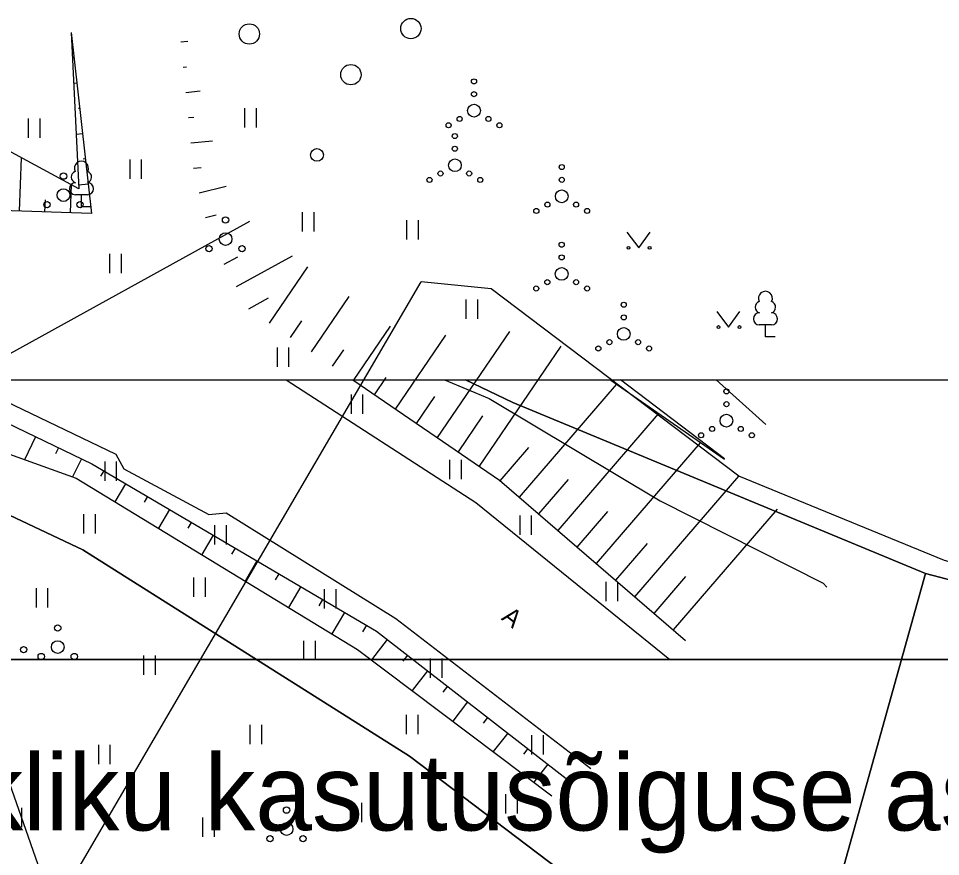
# Model space of a CAD drawing. Extents: x 554947 to 555436, y 6564938 to 6565792.
# Drawn here: x 555027.7 to 555064.02, y 6565636.15 to 6565669.14 of the extents above; entities that cross this region are included whole.
import ezdxf

# ---------------------------------------------------------------- set-up
doc = ezdxf.new("R2010")
doc.units = 0
for name, color, linetype in [('AED', 7, 'Continuous'), ('HALJASTUS', 7, 'Continuous'), ('KPKAABEL', 7, 'Continuous'), ('MPKAABEL', 7, 'Continuous'), ('PIIR', 7, 'Continuous'), ('POST', 7, 'Continuous'), ('PR_SIDE', 7, 'Continuous'), ('PUU', 7, 'Continuous'), ('RELJEEF', 7, 'Continuous'), ('TEE', 7, 'Continuous'), ('VORMISTUS_2', 7, 'Continuous')]:
    doc.layers.add(name, color=color, linetype=linetype)

msp = doc.modelspace()

# ---------------------------------------------------------------- linework, layer by layer
at = {"layer": 'AED'}
msp.add_lwpolyline([(555057.142, 6565653.162), (555055.18, 6565654.913)], dxfattribs=at)
at = {"layer": 'HALJASTUS'}
for p, q in [((555036.611, 6565665.617), (555036.611, 6565664.856)), ((555037.066, 6565665.617), (555037.066, 6565664.856)), ((555028.088, 6565665.207), (555028.088, 6565664.446)), ((555028.543, 6565665.207), (555028.543, 6565664.446)), ((555032.085, 6565663.593), (555032.085, 6565662.832)), ((555032.54, 6565663.593), (555032.54, 6565662.832)), ((555038.874, 6565661.521), (555038.874, 6565660.76)), ((555039.329, 6565661.521), (555039.329, 6565660.76)), ((555042.991, 6565661.208), (555042.991, 6565660.447)), ((555043.446, 6565661.208), (555043.446, 6565660.447)), ((555051.669, 6565660.724), (555052.133, 6565660.117)), ((555052.133, 6565660.117), (555052.578, 6565660.724)), ((555031.29, 6565659.883), (555031.29, 6565659.122)), ((555031.745, 6565659.883), (555031.745, 6565659.122)), ((555045.327, 6565658.076), (555045.327, 6565657.315)), ((555045.782, 6565658.076), (555045.782, 6565657.315)), ((555055.209, 6565657.604), (555055.672, 6565656.997)), ((555055.672, 6565656.997), (555056.118, 6565657.604)), ((555037.887, 6565656.197), (555037.887, 6565655.436)), ((555038.342, 6565656.197), (555038.342, 6565655.436)), ((555040.8, 6565654.342), (555040.8, 6565653.581)), ((555041.255, 6565654.342), (555041.255, 6565653.581)), ((555031.098, 6565651.706), (555031.098, 6565650.945)), ((555031.553, 6565651.706), (555031.553, 6565650.945)), ((555044.676, 6565651.764), (555044.676, 6565651.003)), ((555045.132, 6565651.764), (555045.132, 6565651.003)), ((555030.263, 6565649.635), (555030.263, 6565648.874)), ((555030.718, 6565649.635), (555030.718, 6565648.874)), ((555047.445, 6565649.572), (555047.445, 6565648.811)), ((555047.9, 6565649.572), (555047.9, 6565648.811)), ((555035.423, 6565649.197), (555035.423, 6565648.436)), ((555035.878, 6565649.197), (555035.878, 6565648.436)), ((555034.597, 6565647.143), (555034.597, 6565646.381)), ((555035.052, 6565647.143), (555035.052, 6565646.381)), ((555028.397, 6565646.712), (555028.397, 6565645.951)), ((555028.852, 6565646.712), (555028.852, 6565645.951)), ((555039.741, 6565646.676), (555039.741, 6565645.915)), ((555040.196, 6565646.676), (555040.196, 6565645.915)), ((555050.84, 6565646.97), (555050.84, 6565646.209)), ((555051.295, 6565646.97), (555051.295, 6565646.209)), ((555038.932, 6565644.65), (555038.932, 6565643.889)), ((555039.387, 6565644.65), (555039.387, 6565643.889)), ((555032.631, 6565644.07), (555032.631, 6565643.309)), ((555033.086, 6565644.07), (555033.086, 6565643.309)), ((555043.92, 6565643.947), (555043.92, 6565643.186)), ((555044.375, 6565643.947), (555044.375, 6565643.186)), ((555042.975, 6565641.729), (555042.975, 6565640.968)), ((555043.43, 6565641.729), (555043.43, 6565640.968)), ((555036.817, 6565641.336), (555036.817, 6565640.575)), ((555037.272, 6565641.336), (555037.272, 6565640.575)), ((555047.907, 6565640.93), (555047.907, 6565640.169)), ((555048.362, 6565640.93), (555048.362, 6565640.169)), ((555030.852, 6565640.558), (555030.852, 6565639.797)), ((555031.307, 6565640.558), (555031.307, 6565639.797)), ((555040.764, 6565638.275), (555040.764, 6565637.514)), ((555041.219, 6565638.275), (555041.219, 6565637.514)), ((555046.886, 6565638.615), (555046.886, 6565637.853)), ((555047.341, 6565638.615), (555047.341, 6565637.853)), ((555027.824, 6565638.07), (555027.824, 6565637.309)), ((555028.279, 6565638.07), (555028.279, 6565637.309)), ((555034.953, 6565637.697), (555034.953, 6565636.936)), ((555035.408, 6565637.697), (555035.408, 6565636.936))]:
    msp.add_line(p, q, dxfattribs=at)
msp.add_lwpolyline([(555055.505, 6565651.803), (555051.413, 6565654.913)], dxfattribs=at)
for centre, radius in [((555043.157, 6565668.742), 0.4), ((555036.795, 6565668.531), 0.4), ((555040.797, 6565666.929), 0.4), ((555045.644, 6565666.663), 0.1), ((555045.644, 6565666.163), 0.1), ((555045.644, 6565665.513), 0.25), ((555045.079, 6565665.188), 0.1), ((555046.209, 6565665.188), 0.1), ((555044.644, 6565664.938), 0.1), ((555046.644, 6565664.938), 0.1), ((555044.89, 6565664.513), 0.1), ((555044.89, 6565664.013), 0.1), ((555044.89, 6565663.363), 0.25), ((555049.099, 6565663.291), 0.1), ((555044.325, 6565663.038), 0.1), ((555045.455, 6565663.038), 0.1), ((555043.89, 6565662.788), 0.1), ((555045.89, 6565662.788), 0.1), ((555049.099, 6565662.791), 0.1), ((555049.099, 6565662.141), 0.25), ((555048.534, 6565661.816), 0.1), ((555049.664, 6565661.816), 0.1), ((555048.099, 6565661.566), 0.1), ((555050.099, 6565661.566), 0.1), ((555049.097, 6565660.237), 0.1), ((555051.732, 6565660.117), 0.055), ((555052.561, 6565660.117), 0.055), ((555049.097, 6565659.737), 0.1), ((555049.097, 6565659.087), 0.25), ((555048.097, 6565658.512), 0.1), ((555048.532, 6565658.762), 0.1), ((555049.662, 6565658.762), 0.1), ((555050.097, 6565658.512), 0.1), ((555051.541, 6565657.876), 0.1), ((555051.541, 6565657.376), 0.1), ((555051.541, 6565656.726), 0.25), ((555055.271, 6565656.997), 0.055), ((555056.1, 6565656.997), 0.055), ((555050.976, 6565656.401), 0.1), ((555052.106, 6565656.401), 0.1), ((555050.541, 6565656.151), 0.1), ((555052.541, 6565656.151), 0.1), ((555055.586, 6565654.461), 0.1), ((555055.586, 6565653.961), 0.1), ((555055.586, 6565653.311), 0.25), ((555054.586, 6565652.736), 0.1), ((555055.021, 6565652.986), 0.1), ((555056.151, 6565652.986), 0.1), ((555056.586, 6565652.736), 0.1)]:
    msp.add_circle(centre, radius, dxfattribs=at)
at = {"layer": 'KPKAABEL'}
msp.add_lwpolyline([(555022.085, 6565654.913), (555021.622, 6565652.627), (555021.526, 6565649.765), (555022.786, 6565647.231), (555026.485, 6565641.465), (555030.606, 6565629.728), (555035.378, 6565618.813), (555040.844, 6565608.057), (555047.089, 6565597.805), (555053.567, 6565587.292), (555056.073, 6565583.696), (555062.108, 6565572.667), (555068.248, 6565560.982), (555073.771, 6565549.852), (555080.106, 6565537.978), (555085.958, 6565527.605), (555092.403, 6565515.607), (555098.402, 6565504.536), (555104.641, 6565492.438), (555110.839, 6565480.82), (555116.697, 6565469.072), (555121.821, 6565458.116), (555126.894, 6565446.731), (555132.737, 6565435.388)], dxfattribs=at)
at = {"layer": 'MPKAABEL'}
msp.add_lwpolyline([(555044.483, 6565654.913), (555046.244, 6565654.185), (555052.975, 6565650.153), (555059.391, 6565646.912), (555059.541, 6565646.762)], dxfattribs=at)
at = {"layer": 'PIIR'}
for points in [[(555016.055, 6565654.913), (555030.24, 6565648.23), (555043.11, 6565640.11), (555053.62, 6565632.14), (555056.61, 6565622.91), (555057.22, 6565600.73), (555060.42, 6565583.26), (555065.78, 6565566.7), (555076.76, 6565542.38), (555113.82, 6565475.68), (554946.63, 6565420.78), (554981.01, 6565316.76), (555160.07, 6565375.54), (555166.64, 6565360.5), (555167.67, 6565357.913)], [(555045.31, 6565654.913), (555047.17, 6565654.02), (555063.43, 6565647.29), (555056.61, 6565622.91), (555053.62, 6565632.14), (555043.11, 6565640.11), (555030.24, 6565648.23), (555016.055, 6565654.913)], [(555140.201, 6565654.913), (555137.2, 6565645.72), (555136.5, 6565633.07), (555130.73, 6565621.32), (555129.77, 6565611.2), (555114.24, 6565634), (555063.43, 6565647.29), (555047.17, 6565654.02), (555045.31, 6565654.913)], [(555144.16, 6565410.6), (555124.27, 6565454.45), (555113.82, 6565475.68), (555076.76, 6565542.38), (555065.78, 6565566.7), (555060.42, 6565583.26), (555057.22, 6565600.73), (555056.61, 6565622.91), (555063.43, 6565647.29), (555114.24, 6565634), (555129.77, 6565611.2), (555130.73, 6565621.32), (555138.66, 6565615.26), (555160.12, 6565598.86), (555193.24, 6565604.68), (555193.7, 6565602.7), (555225.47, 6565605.89), (555234.35, 6565605.6), (555251.24, 6565598.48), (555330.71, 6565538.85), (555343.81, 6565536.56), (555350.68, 6565540.44), (555361.56, 6565549.57), (555393.069, 6565582.099)]]:
    msp.add_lwpolyline(points, dxfattribs=at)
at = {"layer": 'POST'}
msp.add_circle((555039.46, 6565663.773), 0.25, dxfattribs=at)
at = {"layer": 'PR_SIDE'}
for points in [[(555136.7, 6565433.435), (555128.282, 6565452.724), (555120.742, 6565469.061), (555112.406, 6565484.723), (555103.739, 6565501.239), (555091.881, 6565522.261), (555081.894, 6565540.539), (555077.43, 6565548.48), (555070.988, 6565563.058), (555062.867, 6565584.513), (555061.059, 6565592.839), (555060.376, 6565594.02), (555051.547, 6565599.57), (555040.593, 6565606.013), (555035.25, 6565616.948), (555028.135, 6565630.971), (555028.178, 6565632.46), (555043.563, 6565658.774)], [(555093.45, 6565648.677), (555083.692, 6565642.526), (555064.179, 6565647.804), (555056.079, 6565651.133), (555046.326, 6565658.494), (555043.563, 6565658.774)]]:
    msp.add_lwpolyline(points, dxfattribs=at)
at = {"layer": 'PUU'}
for p, q in [((555030.422, 6565662.201), (555029.942, 6565662.201)), ((555030.182, 6565661.726), (555030.182, 6565662.201)), ((555030.562, 6565661.726), (555030.182, 6565661.726)), ((555057.361, 6565657.08), (555056.881, 6565657.08)), ((555057.121, 6565656.605), (555057.121, 6565657.08)), ((555057.501, 6565656.605), (555057.121, 6565656.605))]:
    msp.add_line(p, q, dxfattribs=at)
for centre, radius in [((555029.476, 6565662.937), 0.125), ((555029.476, 6565662.187), 0.25), ((555028.826, 6565661.812), 0.125), ((555030.126, 6565661.812), 0.125), ((555035.859, 6565661.208), 0.125), ((555035.859, 6565660.458), 0.25), ((555035.209, 6565660.083), 0.125), ((555036.509, 6565660.083), 0.125), ((555029.249, 6565645.151), 0.125), ((555029.249, 6565644.401), 0.25), ((555027.906, 6565644.299), 0.125), ((555028.599, 6565644.026), 0.125), ((555029.899, 6565644.026), 0.125), ((555038.26, 6565637.984), 0.125), ((555038.26, 6565637.234), 0.25), ((555037.61, 6565636.859), 0.125), ((555038.91, 6565636.859), 0.125)]:
    msp.add_circle(centre, radius, dxfattribs=at)
for centre, radius, start, end in [((555030.182, 6565663.246), 0.277, 332.5799, 207.4201), ((555030.012, 6565662.899), 0.233, 109.0217, 253.1415), ((555030.352, 6565662.899), 0.233, 286.8508, 70.9859), ((555029.944, 6565662.439), 0.238, 90.0016, 269.3953), ((555030.419, 6565662.439), 0.238, 270.6047, 89.9984), ((555057.121, 6565658.125), 0.277, 332.5799, 207.4201), ((555056.951, 6565657.777), 0.233, 109.0217, 253.1415), ((555057.292, 6565657.777), 0.233, 286.8508, 70.9859), ((555056.884, 6565657.317), 0.238, 90.0016, 269.3953), ((555057.359, 6565657.317), 0.238, 270.6047, 89.9984)]:
    msp.add_arc(centre, radius, start, end, dxfattribs=at)
at = {"layer": 'RELJEEF'}
for p, q in [((555034.094, 6565668.222), (555034.378, 6565668.251)), ((555029.894, 6565667.589), (555029.875, 6565667.587)), ((555034.194, 6565667.227), (555034.322, 6565667.24)), ((555030.005, 6565666.595), (555029.88, 6565666.581)), ((555034.294, 6565666.232), (555034.863, 6565666.29)), ((555030.116, 6565665.601), (555030.06, 6565665.595)), ((555034.395, 6565665.237), (555034.608, 6565665.259)), ((555030.227, 6565664.607), (555029.978, 6565664.579)), ((555034.495, 6565664.242), (555035.348, 6565664.328)), ((555027.747, 6565661.559), (555027.82, 6565663.662)), ((555030.338, 6565663.613), (555030.244, 6565663.603)), ((555034.595, 6565663.247), (555034.893, 6565663.277)), ((555029.745, 6565661.489), (555029.785, 6565662.602)), ((555030.448, 6565662.62), (555030.075, 6565662.578)), ((555034.815, 6565662.274), (555035.879, 6565662.546)), ((555028.746, 6565661.524), (555028.763, 6565662.006)), ((555025.494, 6565654.913), (555036.813, 6565661.164)), ((555035.063, 6565661.305), (555035.486, 6565661.413)), ((555035.804, 6565659.465), (555036.34, 6565659.761)), ((555036.288, 6565658.589), (555038.489, 6565659.805)), ((555037.592, 6565657.146), (555039.103, 6565659.364)), ((555036.771, 6565657.714), (555037.556, 6565658.148)), ((555039.245, 6565656.02), (555040.728, 6565658.196)), ((555038.419, 6565656.583), (555038.868, 6565657.242)), ((555040.898, 6565654.894), (555042.352, 6565657.028)), ((555044.204, 6565652.642), (555047.053, 6565656.823)), ((555042.551, 6565653.768), (555044.529, 6565656.67)), ((555040.072, 6565655.457), (555040.512, 6565656.103)), ((555045.856, 6565651.515), (555049.075, 6565656.24)), ((555041.724, 6565654.331), (555042.187, 6565655.01)), ((555047.438, 6565650.296), (555051.257, 6565654.729)), ((555043.377, 6565653.205), (555044.101, 6565654.267)), ((555048.953, 6565648.99), (555052.911, 6565653.584)), ((555045.03, 6565652.078), (555045.997, 6565653.498)), ((555028.377, 6565652.677), (555027.942, 6565651.775)), ((555050.468, 6565647.685), (555054.564, 6565652.439)), ((555029.278, 6565652.243), (555029.161, 6565652)), ((555046.68, 6565650.949), (555047.805, 6565652.254)), ((555030.179, 6565651.808), (555029.835, 6565651.095)), ((555031.059, 6565651.335), (555030.935, 6565651.125)), ((555048.195, 6565649.643), (555049.362, 6565650.997)), ((555051.983, 6565646.379), (555056.079, 6565651.133)), ((555031.921, 6565650.828), (555031.502, 6565650.115)), ((555032.783, 6565650.322), (555032.655, 6565650.104)), ((555033.646, 6565649.816), (555033.212, 6565649.076)), ((555049.71, 6565648.338), (555050.919, 6565649.74)), ((555053.498, 6565645.074), (555057.594, 6565649.828)), ((555034.508, 6565649.309), (555034.375, 6565649.084)), ((555035.37, 6565648.803), (555034.921, 6565648.037)), ((555051.225, 6565647.032), (555052.475, 6565648.482)), ((555036.233, 6565648.297), (555036.096, 6565648.063)), ((555037.095, 6565647.79), (555036.63, 6565646.998)), ((555037.957, 6565647.284), (555037.816, 6565647.042)), ((555052.741, 6565645.727), (555053.99, 6565647.177)), ((555038.82, 6565646.778), (555038.339, 6565645.959)), ((555039.682, 6565646.271), (555039.536, 6565646.022)), ((555040.544, 6565645.765), (555040.048, 6565644.92)), ((555041.407, 6565645.258), (555041.256, 6565645.001)), ((555042.23, 6565644.695), (555041.608, 6565643.893)), ((555043.02, 6565644.082), (555042.836, 6565643.845)), ((555043.81, 6565643.469), (555043.206, 6565642.69)), ((555044.6, 6565642.855), (555044.422, 6565642.625)), ((555045.39, 6565642.242), (555044.804, 6565641.487)), ((555046.18, 6565641.629), (555046.007, 6565641.406)), ((555046.97, 6565641.016), (555046.402, 6565640.284)), ((555047.76, 6565640.403), (555047.592, 6565640.187)), ((555048.55, 6565639.79), (555048, 6565639.082))]:
    msp.add_line(p, q, dxfattribs=at)
for points in [[(555029.783, 6565668.583), (555030.578, 6565661.46), (555027.05, 6565661.583), (555020.786, 6565664.508)], [(555029.783, 6565668.583), (555030.081, 6565662.441), (555021.007, 6565667.338)], [(555017.568, 6565657.887), (555030.588, 6565651.611), (555041.809, 6565645.022), (555049.395, 6565639.133)], [(555016.649, 6565655.832), (555029.972, 6565651.046), (555041.058, 6565644.307), (555048.71, 6565638.547)], [(555040.87, 6565654.913), (555046.65, 6565650.974), (555053.976, 6565644.662)], [(555055.507, 6565651.786), (555050.991, 6565654.913)]]:
    msp.add_lwpolyline(points, dxfattribs=at)
at = {"layer": 'TEE'}
for points in [[(555017.828, 6565658.565), (555031.536, 6565651.986), (555031.846, 6565651.41), (555035.205, 6565649.618), (555035.879, 6565649.677), (555042.559, 6565645.526), (555050.244, 6565639.614)], [(555038.252, 6565654.913), (555045.718, 6565650.093), (555053.358, 6565643.906)]]:
    msp.add_lwpolyline(points, dxfattribs=at)
at = {"layer": 'VORMISTUS_2'}
for points in [[(554999.363, 6565654.913), (555209.363, 6565654.913), (555209.363, 6565357.913), (554999.363, 6565357.913)], [(555009.363, 6565368.913), (555199.363, 6565368.913), (555199.363, 6565643.913), (555009.363, 6565643.913)], [(555009.363, 6565643.913), (555199.363, 6565643.913), (555199.363, 6565368.913), (555009.363, 6565368.913)]]:
    msp.add_lwpolyline(points, close=True, dxfattribs=at)

# ---------------------------------------------------------------- texts
at = {"layer": 'TEE'}
msp.add_text('A', height=0.7, rotation=321.6468, dxfattribs=at).set_placement((555046.687, 6565645.499))
at = {"layer": 'VORMISTUS_2'}
msp.add_text('Isikliku kasutusõiguse asendiplaan', height=3, dxfattribs=at).set_placement((555021.874, 6565637.182))

doc.saveas('drawing.dxf')
